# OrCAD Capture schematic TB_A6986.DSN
size C
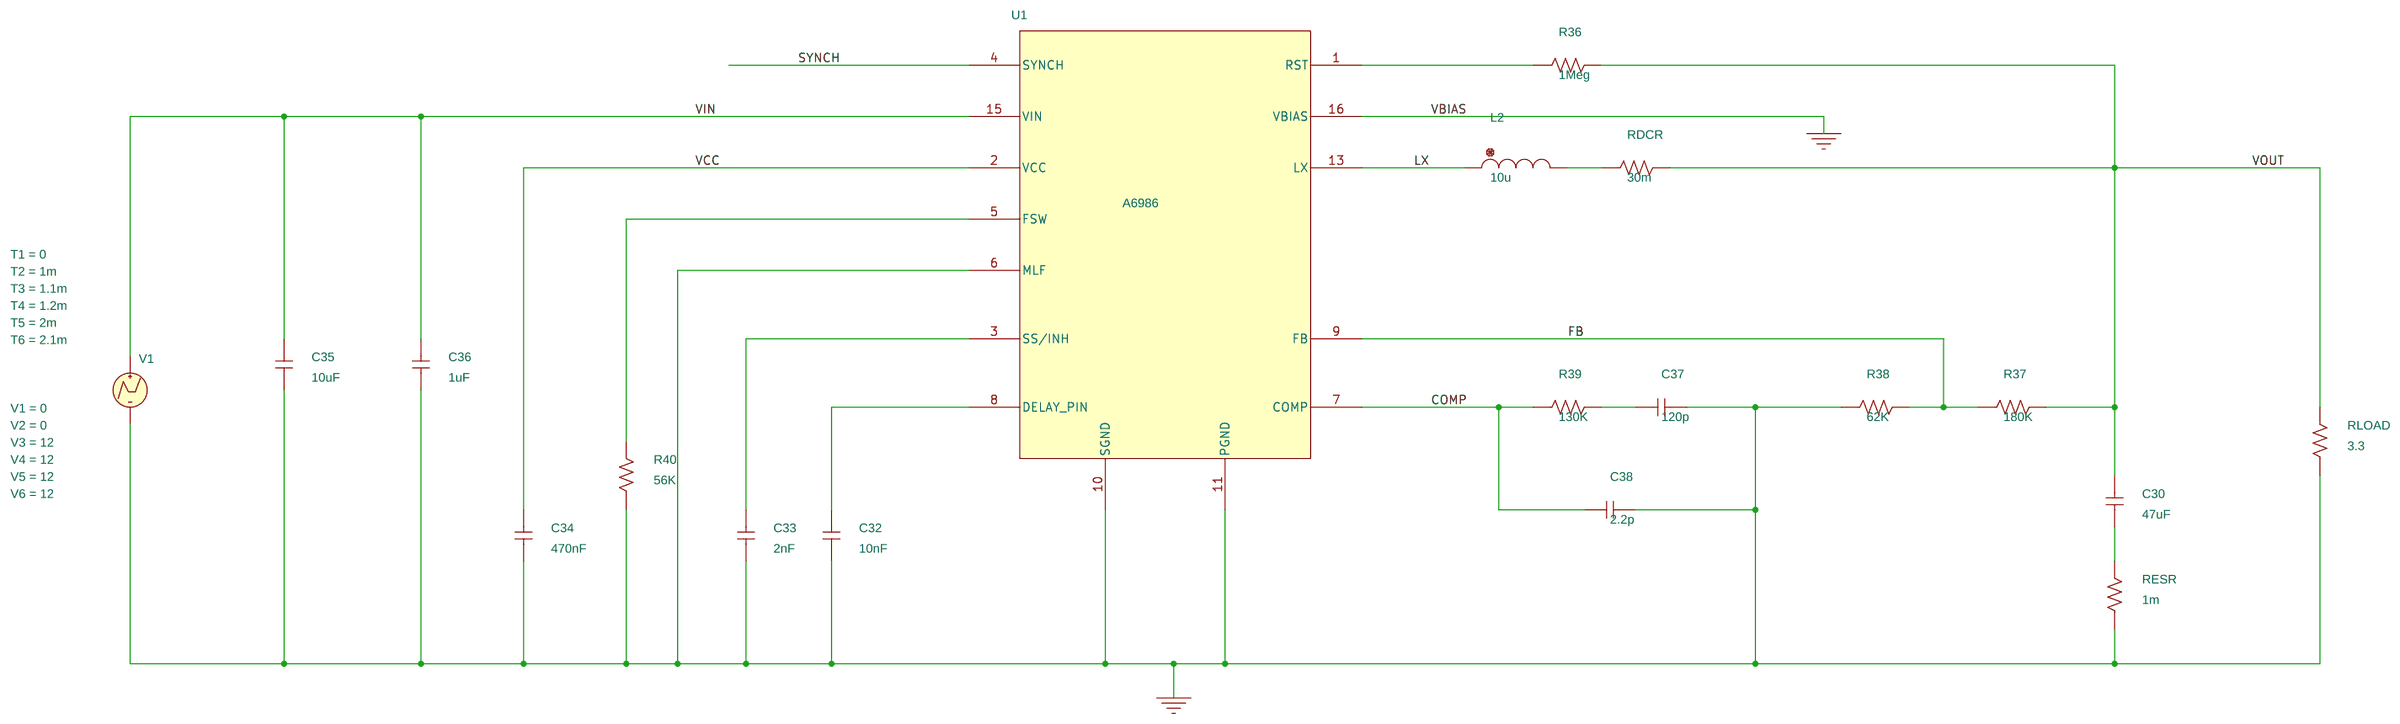
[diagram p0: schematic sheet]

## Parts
C30  47uF  [RAD/CK05]
C32  10nF  [RAD/CK05]
C33  2nF  [RAD/CK05]
C34  470nF  [RAD/CK05]
C35  10uF  [RAD/CK05]
C36  1uF  [RAD/CK05]
C37  120p  [RAD/CK05]
C38  2.2p  [RAD/CK05]
L2  10u  [DISC/.350x.175/LS.200x.100/.034]
R36  1Meg  [AX/RC05]
R37  180K  [AX/RC05]
R38  62K  [AX/RC05]
R39  130K  [AX/RC05]
R40  56K  [AX/RC05]
RDCR  30m  [AX/RC05]
RESR  1m  [AX/RC05]
RLOAD  3.3  [AX/RC05]
U1  A6986
V1  VPWL

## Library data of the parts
C30 = C: IC: 0
C32-C38 = C
L2 = L
R36-R40 RDCR RESR RLOAD = R
U1 = A6986
V1 = VPWL: T1: 0; T2: 1m; T3: 1.1m; T4: 1.2m; T5: 2m; T6: 2.1m; V1: 0; V2: 0; V3: 12; V4: 12; V5: 12; V6: 12

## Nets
VCC: C34.2 U1.2(VCC)
VIN: C35.2 C36.2 U1.15(VIN) V1.1(+)
0: C32.1 C33.1 C34.1 C35.1 C36.1 C37.2 C38.2 R38.1 R40.1 RESR.1 RLOAD.1 U1.6(MLF) U1.10(SGND) U1.11(PGND) U1.16(VBIAS) V1.2(-)
COMP: C38.1 R39.1 U1.7(COMP)
FB: R37.1 R38.2 U1.9(FB)
LX: L2.1 U1.13(LX)
SYNCH: U1.4(SYNCH)
VOUT: C30.1 R36.2 R37.2 RDCR.2 RLOAD.2
N3805589: C30.2 RESR.2
N3805777: R36.1 U1.1(RST)
N3805847: C32.2 U1.8(DELAY_PIN)
N3805881: C33.2 U1.3(SS/INH)
N3806117: C37.1 R39.2
N3808463: L2.2 RDCR.1
N3808680: R40.2 U1.5(FSW)
